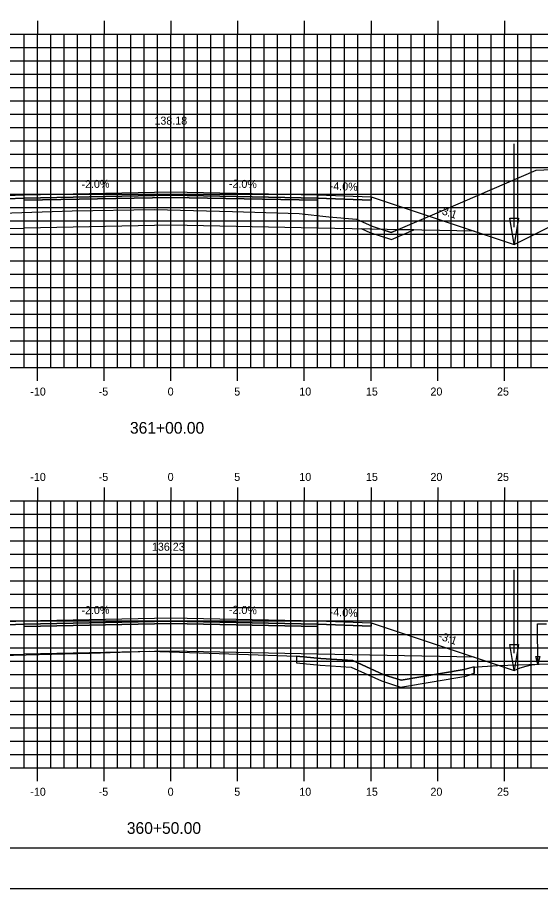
# Model space of a CAD drawing. Extents: x 1146525 to 1146695, y 608981 to 609091.
# Drawn here: x 1146596.2 to 1146635.4, y 608981.3 to 609046.6 of the extents above; entities that cross this region are included whole.
import ezdxf

# ---------------------------------------------------------------- set-up
doc = ezdxf.new("R2010")
doc.units = 0
for name, color, linetype in [('ANNOTATION', 7, 'Continuous'), ('BORDER', 7, 'Continuous'), ('D_Drainage_Ditch_Line', 7, 'Continuous'), ('D_Roadway_Centerline', 7, 'Continuous'), ('D_Roadway_Centerline_Text', 7, 'Continuous'), ('D_Roadway_Edge_Shoulder', 7, 'Continuous'), ('D_Roadway_Edge_TW', 7, 'Continuous'), ('D_Roadway_Pavement', 7, 'Continuous'), ('D_Roadway_SlopeLines', 7, 'Continuous'), ('D_Roadway_SubGrade', 7, 'Continuous'), ('D_Text_Standard', 7, 'Continuous'), ('H_V ANNOTATION', 7, 'Continuous'), ('MAJOR', 7, 'Continuous'), ('MINOR', 7, 'Continuous'), ('PLOT BOUNDARY', 7, 'Continuous'), ('S_Roadway_Centerline', 7, 'Continuous'), ('SHADING', 7, 'Continuous')]:
    doc.layers.add(name, color=color, linetype=linetype)

msp = doc.modelspace()

# ---------------------------------------------------------------- linework, layer by layer
for points in [[(1146573.905, 609032.428), (1146575.155, 609032.306), (1146576.405, 609032.04), (1146577.655, 609031.631), (1146578.905, 609031.077), (1146581.947, 609029.556), (1146584.947, 609030.556), (1146592.67, 609033.131), (1146592.671, 609033.131), (1146596.671, 609033.291), (1146607.671, 609033.511), (1146618.671, 609033.291), (1146622.671, 609033.131), (1146630.395, 609030.556), (1146633.395, 609029.556), (1146642.977, 609034.348), (1146644.227, 609034.902), (1146645.477, 609035.313), (1146646.727, 609035.583), (1146647.977, 609035.71)], [(1146573.921, 608998.789), (1146575.081, 608998.68), (1146576.241, 608998.437), (1146577.401, 608998.059), (1146578.562, 608997.547), (1146581.562, 608998.547), (1146589.055, 609001.044), (1146589.056, 609001.044), (1146596.671, 609001.349), (1146607.671, 609001.569), (1146618.671, 609001.349), (1146622.671, 609001.189), (1146630.395, 608998.614), (1146633.395, 608997.614), (1146633.841, 608997.812), (1146634.287, 608997.957), (1146634.734, 608998.049), (1146635.18, 608998.09)]]:
    msp.add_lwpolyline(points)
at = {"layer": 'BORDER'}
msp.add_lwpolyline([(1146532.671, 608984.335), (1146692.671, 608984.335), (1146692.671, 609089.335), (1146532.671, 609089.335)], close=True, dxfattribs=at)
at = {"layer": 'D_Drainage_Ditch_Line'}
for p, q in [((1146633.395, 609030.869), (1146633.395, 609037.112)), ((1146633.395, 608998.927), (1146633.395, 609005.17))]:
    msp.add_line(p, q, dxfattribs=at)
for points in [[(1146633.067, 609031.525), (1146633.723, 609031.525), (1146633.395, 609029.556)], [(1146633.067, 608999.583), (1146633.723, 608999.583), (1146633.395, 608997.614)]]:
    msp.add_lwpolyline(points, close=True, dxfattribs=at)
at = {"layer": 'D_Roadway_Edge_Shoulder'}
for points in [[(1146596.671, 609033.291), (1146592.671, 609033.131), (1146592.671, 609032.881), (1146596.671, 609033.041)], [(1146618.671, 609033.291), (1146622.671, 609033.131), (1146622.671, 609032.881), (1146618.671, 609033.041)], [(1146596.671, 609001.349), (1146590.841, 609001.116), (1146590.841, 609000.866), (1146596.671, 609001.099)], [(1146618.671, 609001.349), (1146622.671, 609001.189), (1146622.671, 609000.939), (1146618.671, 609001.099)]]:
    msp.add_lwpolyline(points, close=True, dxfattribs=at)
at = {"layer": 'D_Roadway_Edge_TW'}
for points in [[(1146596.671, 609033.041), (1146596.671, 609033.291), (1146607.671, 609033.511), (1146618.671, 609033.291), (1146618.671, 609033.041), (1146607.671, 609033.261)], [(1146596.671, 609001.099), (1146596.671, 609001.349), (1146607.671, 609001.569), (1146618.671, 609001.349), (1146618.671, 609001.099), (1146607.671, 609001.319)]]:
    msp.add_lwpolyline(points, close=True, dxfattribs=at)
at = {"layer": 'D_Roadway_Pavement'}
for points in [[(1146596.671, 609032.874), (1146596.671, 609033.041), (1146607.671, 609033.261), (1146618.671, 609033.041), (1146618.671, 609032.874), (1146607.671, 609033.094)], [(1146596.671, 609000.932), (1146596.671, 609001.099), (1146607.671, 609001.319), (1146618.671, 609001.099), (1146618.671, 609000.932), (1146607.671, 609001.152)]]:
    msp.add_lwpolyline(points, close=True, dxfattribs=at)
at = {"layer": 'D_Roadway_SlopeLines'}
for points in [[(1146633.395, 609029.556), (1146642.977, 609034.348), (1146644.227, 609034.902), (1146645.477, 609035.313), (1146646.727, 609035.583), (1146647.977, 609035.71)], [(1146630.395, 609030.556), (1146633.395, 609029.556)], [(1146630.395, 608998.614), (1146633.395, 608997.614)], [(1146633.395, 608997.614), (1146633.841, 608997.812), (1146634.287, 608997.957), (1146634.734, 608998.049), (1146635.18, 608998.09)]]:
    msp.add_lwpolyline(points, dxfattribs=at)
at = {"layer": 'D_Roadway_SubGrade'}
for p, q in [((1146617.098, 608998.7), (1146617.098, 608998.2)), ((1146630.395, 608997.893), (1146630.395, 608997.393))]:
    msp.add_line(p, q, dxfattribs=at)
for points in [[(1146596.671, 609032.874), (1146596.671, 609033.041), (1146592.671, 609032.881), (1146592.671, 609033.131), (1146592.67, 609033.131), (1146584.947, 609030.556), (1146596.671, 609030.791)], [(1146596.671, 609030.791), (1146596.671, 609032.874), (1146607.671, 609033.094), (1146618.671, 609032.874), (1146618.671, 609030.791), (1146607.671, 609031.011)], [(1146618.671, 609032.874), (1146618.671, 609033.041), (1146622.671, 609032.881), (1146622.671, 609033.131), (1146622.671, 609033.131), (1146630.395, 609030.556), (1146618.671, 609030.791)], [(1146596.671, 609000.932), (1146596.671, 609001.099), (1146590.841, 609000.866), (1146590.841, 609001.116), (1146590.84, 609001.116), (1146583.233, 608998.58), (1146596.671, 608998.849)], [(1146596.671, 608998.849), (1146596.671, 609000.932), (1146607.671, 609001.152), (1146618.671, 609000.932), (1146618.671, 608998.849), (1146607.671, 608999.069)], [(1146618.671, 609000.932), (1146618.671, 609001.099), (1146622.671, 609000.939), (1146622.671, 609001.189), (1146622.671, 609001.189), (1146630.395, 608998.614), (1146618.671, 608998.849)]]:
    msp.add_lwpolyline(points, close=True, dxfattribs=at)
for points in [[(1146621.982, 609030.725), (1146622.578, 609030.463), (1146624.206, 609029.935), (1146625.88, 609030.647)], [(1146621.982, 609030.725), (1146622.578, 609030.463), (1146624.206, 609029.935), (1146625.88, 609030.647)], [(1146617.098, 608998.199), (1146618.862, 608998.035), (1146621.178, 608997.872), (1146623.445, 608996.845), (1146624.881, 608996.377), (1146629.778, 608997.211), (1146630.334, 608997.39), (1146630.395, 608997.393)]]:
    msp.add_lwpolyline(points, dxfattribs=at)
at = {"layer": 'D_Text_Standard'}
msp.add_lwpolyline([(1146635.18, 608998.09), (1146635.15, 609001.127), (1146635.83, 609001.127)], dxfattribs=at)
msp.add_lwpolyline([(1146635.18, 608998.09), (1146635.029, 608998.671), (1146635.32, 608998.674)], close=True, dxfattribs=at)
at = {"layer": 'MAJOR'}
for p, q in [((1146597.671, 609046.337), (1146597.671, 609045.335)), ((1146602.671, 609046.337), (1146602.671, 609045.335)), ((1146607.671, 609046.337), (1146607.671, 609045.335)), ((1146612.671, 609046.337), (1146612.671, 609045.335)), ((1146617.671, 609046.337), (1146617.671, 609045.335)), ((1146622.671, 609046.337), (1146622.671, 609045.335)), ((1146627.671, 609046.337), (1146627.671, 609045.335)), ((1146632.671, 609046.337), (1146632.671, 609045.335)), ((1146537.671, 609045.335), (1146677.671, 609045.335)), ((1146537.671, 609045.335), (1146677.671, 609045.335)), ((1146597.671, 609020.335), (1146597.671, 609045.335)), ((1146602.671, 609020.335), (1146602.671, 609045.335)), ((1146607.671, 609020.335), (1146607.671, 609045.335)), ((1146612.671, 609020.335), (1146612.671, 609045.335)), ((1146617.671, 609020.335), (1146617.671, 609045.335)), ((1146622.671, 609020.335), (1146622.671, 609045.335)), ((1146627.671, 609020.335), (1146627.671, 609045.335)), ((1146632.671, 609020.335), (1146632.671, 609045.335)), ((1146537.671, 609040.335), (1146677.671, 609040.335)), ((1146537.671, 609035.335), (1146677.671, 609035.335)), ((1146537.671, 609030.335), (1146677.671, 609030.335)), ((1146537.671, 609025.335), (1146677.671, 609025.335)), ((1146537.671, 609020.335), (1146677.671, 609020.335)), ((1146537.671, 609020.335), (1146677.671, 609020.335)), ((1146597.671, 609019.333), (1146597.671, 609020.335)), ((1146602.671, 609019.333), (1146602.671, 609020.335)), ((1146607.671, 609019.333), (1146607.671, 609020.335)), ((1146612.671, 609019.333), (1146612.671, 609020.335)), ((1146617.671, 609019.333), (1146617.671, 609020.335)), ((1146622.671, 609019.333), (1146622.671, 609020.335)), ((1146627.671, 609019.333), (1146627.671, 609020.335)), ((1146632.671, 609019.333), (1146632.671, 609020.335)), ((1146597.671, 609011.337), (1146597.671, 609010.335)), ((1146602.671, 609011.337), (1146602.671, 609010.335)), ((1146607.671, 609011.337), (1146607.671, 609010.335)), ((1146612.671, 609011.337), (1146612.671, 609010.335)), ((1146617.671, 609011.337), (1146617.671, 609010.335)), ((1146622.671, 609011.337), (1146622.671, 609010.335)), ((1146627.671, 609011.337), (1146627.671, 609010.335)), ((1146632.671, 609011.337), (1146632.671, 609010.335)), ((1146537.671, 609010.335), (1146677.671, 609010.335)), ((1146537.671, 609010.335), (1146677.671, 609010.335)), ((1146597.671, 608990.335), (1146597.671, 609010.335)), ((1146602.671, 608990.335), (1146602.671, 609010.335)), ((1146607.671, 608990.335), (1146607.671, 609010.335)), ((1146612.671, 608990.335), (1146612.671, 609010.335)), ((1146617.671, 608990.335), (1146617.671, 609010.335)), ((1146622.671, 608990.335), (1146622.671, 609010.335)), ((1146627.671, 608990.335), (1146627.671, 609010.335)), ((1146632.671, 608990.335), (1146632.671, 609010.335)), ((1146537.671, 609005.335), (1146677.671, 609005.335)), ((1146537.671, 609000.335), (1146677.671, 609000.335)), ((1146537.671, 608995.335), (1146677.671, 608995.335)), ((1146537.671, 608990.335), (1146677.671, 608990.335)), ((1146537.671, 608990.335), (1146677.671, 608990.335)), ((1146597.671, 608989.333), (1146597.671, 608990.335)), ((1146602.671, 608989.333), (1146602.671, 608990.335)), ((1146607.671, 608989.333), (1146607.671, 608990.335)), ((1146612.671, 608989.333), (1146612.671, 608990.335)), ((1146617.671, 608989.333), (1146617.671, 608990.335)), ((1146622.671, 608989.333), (1146622.671, 608990.335)), ((1146627.671, 608989.333), (1146627.671, 608990.335)), ((1146632.671, 608989.333), (1146632.671, 608990.335))]:
    msp.add_line(p, q, dxfattribs=at)
at = {"layer": 'MINOR'}
for p, q in [((1146596.671, 609020.335), (1146596.671, 609045.335)), ((1146598.671, 609020.335), (1146598.671, 609045.335)), ((1146599.671, 609020.335), (1146599.671, 609045.335)), ((1146600.671, 609020.335), (1146600.671, 609045.335)), ((1146601.671, 609020.335), (1146601.671, 609045.335)), ((1146603.671, 609020.335), (1146603.671, 609045.335)), ((1146604.671, 609020.335), (1146604.671, 609045.335)), ((1146605.671, 609020.335), (1146605.671, 609045.335)), ((1146606.671, 609020.335), (1146606.671, 609045.335)), ((1146608.671, 609020.335), (1146608.671, 609045.335)), ((1146609.671, 609020.335), (1146609.671, 609045.335)), ((1146610.671, 609020.335), (1146610.671, 609045.335)), ((1146611.671, 609020.335), (1146611.671, 609045.335)), ((1146613.671, 609020.335), (1146613.671, 609045.335)), ((1146614.671, 609020.335), (1146614.671, 609045.335)), ((1146615.671, 609020.335), (1146615.671, 609045.335)), ((1146616.671, 609020.335), (1146616.671, 609045.335)), ((1146618.671, 609020.335), (1146618.671, 609045.335)), ((1146619.671, 609020.335), (1146619.671, 609045.335)), ((1146620.671, 609020.335), (1146620.671, 609045.335)), ((1146621.671, 609020.335), (1146621.671, 609045.335)), ((1146623.671, 609020.335), (1146623.671, 609045.335)), ((1146624.671, 609020.335), (1146624.671, 609045.335)), ((1146625.671, 609020.335), (1146625.671, 609045.335)), ((1146626.671, 609020.335), (1146626.671, 609045.335)), ((1146628.671, 609020.335), (1146628.671, 609045.335)), ((1146629.671, 609020.335), (1146629.671, 609045.335)), ((1146630.671, 609020.335), (1146630.671, 609045.335)), ((1146631.671, 609020.335), (1146631.671, 609045.335)), ((1146633.671, 609020.335), (1146633.671, 609045.335)), ((1146634.671, 609020.335), (1146634.671, 609045.335)), ((1146537.671, 609044.335), (1146677.671, 609044.335)), ((1146537.671, 609043.335), (1146677.671, 609043.335)), ((1146537.671, 609042.335), (1146677.671, 609042.335)), ((1146537.671, 609041.335), (1146677.671, 609041.335)), ((1146537.671, 609039.335), (1146677.671, 609039.335)), ((1146537.671, 609038.335), (1146677.671, 609038.335)), ((1146537.671, 609037.335), (1146677.671, 609037.335)), ((1146537.671, 609036.335), (1146677.671, 609036.335)), ((1146537.671, 609034.335), (1146677.671, 609034.335)), ((1146537.671, 609033.335), (1146677.671, 609033.335)), ((1146537.671, 609032.335), (1146677.671, 609032.335)), ((1146537.671, 609031.335), (1146677.671, 609031.335)), ((1146537.671, 609029.335), (1146677.671, 609029.335)), ((1146537.671, 609028.335), (1146677.671, 609028.335)), ((1146537.671, 609027.335), (1146677.671, 609027.335)), ((1146537.671, 609026.335), (1146677.671, 609026.335)), ((1146537.671, 609024.335), (1146677.671, 609024.335)), ((1146537.671, 609023.335), (1146677.671, 609023.335)), ((1146537.671, 609022.335), (1146677.671, 609022.335)), ((1146537.671, 609021.335), (1146677.671, 609021.335)), ((1146596.671, 608990.335), (1146596.671, 609010.335)), ((1146598.671, 608990.335), (1146598.671, 609010.335)), ((1146599.671, 608990.335), (1146599.671, 609010.335)), ((1146600.671, 608990.335), (1146600.671, 609010.335)), ((1146601.671, 608990.335), (1146601.671, 609010.335)), ((1146603.671, 608990.335), (1146603.671, 609010.335)), ((1146604.671, 608990.335), (1146604.671, 609010.335)), ((1146605.671, 608990.335), (1146605.671, 609010.335)), ((1146606.671, 608990.335), (1146606.671, 609010.335)), ((1146608.671, 608990.335), (1146608.671, 609010.335)), ((1146609.671, 608990.335), (1146609.671, 609010.335)), ((1146610.671, 608990.335), (1146610.671, 609010.335)), ((1146611.671, 608990.335), (1146611.671, 609010.335)), ((1146613.671, 608990.335), (1146613.671, 609010.335)), ((1146614.671, 608990.335), (1146614.671, 609010.335)), ((1146615.671, 608990.335), (1146615.671, 609010.335)), ((1146616.671, 608990.335), (1146616.671, 609010.335)), ((1146618.671, 608990.335), (1146618.671, 609010.335)), ((1146619.671, 608990.335), (1146619.671, 609010.335)), ((1146620.671, 608990.335), (1146620.671, 609010.335)), ((1146621.671, 608990.335), (1146621.671, 609010.335)), ((1146623.671, 608990.335), (1146623.671, 609010.335)), ((1146624.671, 608990.335), (1146624.671, 609010.335)), ((1146625.671, 608990.335), (1146625.671, 609010.335)), ((1146626.671, 608990.335), (1146626.671, 609010.335)), ((1146628.671, 608990.335), (1146628.671, 609010.335)), ((1146629.671, 608990.335), (1146629.671, 609010.335)), ((1146630.671, 608990.335), (1146630.671, 609010.335)), ((1146631.671, 608990.335), (1146631.671, 609010.335)), ((1146633.671, 608990.335), (1146633.671, 609010.335)), ((1146634.671, 608990.335), (1146634.671, 609010.335)), ((1146537.671, 609009.335), (1146677.671, 609009.335)), ((1146537.671, 609008.335), (1146677.671, 609008.335)), ((1146537.671, 609007.335), (1146677.671, 609007.335)), ((1146537.671, 609006.335), (1146677.671, 609006.335)), ((1146537.671, 609004.335), (1146677.671, 609004.335)), ((1146537.671, 609003.335), (1146677.671, 609003.335)), ((1146537.671, 609002.335), (1146677.671, 609002.335)), ((1146537.671, 609001.335), (1146677.671, 609001.335)), ((1146537.671, 608999.335), (1146677.671, 608999.335)), ((1146537.671, 608998.335), (1146677.671, 608998.335)), ((1146537.671, 608997.335), (1146677.671, 608997.335)), ((1146537.671, 608996.335), (1146677.671, 608996.335)), ((1146537.671, 608994.335), (1146677.671, 608994.335)), ((1146537.671, 608993.335), (1146677.671, 608993.335)), ((1146537.671, 608992.335), (1146677.671, 608992.335)), ((1146537.671, 608991.335), (1146677.671, 608991.335))]:
    msp.add_line(p, q, dxfattribs=at)
at = {"layer": 'PLOT BOUNDARY'}
msp.add_lwpolyline([(1146524.578, 608981.276), (1146694.578, 608981.276), (1146694.578, 609091.276), (1146524.578, 609091.276)], close=True, dxfattribs=at)
at = {"layer": 'S_Roadway_Centerline'}
for points in [[(1146557.189, 609033.149), (1146565.05, 609032.785), (1146581.825, 609032.109), (1146584.311, 609031.657), (1146589.374, 609030.827), (1146592.033, 609031.484), (1146593.468, 609031.837), (1146594.03, 609031.88), (1146595.014, 609031.905), (1146600.278, 609032.092), (1146606.448, 609032.182), (1146612.282, 609032.042), (1146617.286, 609031.872), (1146619.517, 609031.64), (1146621.574, 609031.449), (1146622.756, 609030.931), (1146624.182, 609030.468), (1146629.549, 609032.75), (1146635.043, 609035.129), (1146648.103, 609035.716), (1146654.911, 609035.417)], [(1146558.972, 608999.325), (1146561.084, 608999.24), (1146581.4, 608998.525), (1146588.809, 608997.707), (1146588.862, 608997.698), (1146592.979, 608998.756), (1146592.988, 608998.759), (1146592.993, 608998.758), (1146594.907, 608998.757), (1146601.66, 608998.911), (1146606.094, 608999.07), (1146612.762, 608998.848), (1146617.098, 608998.7), (1146618.903, 608998.533), (1146621.302, 608998.363), (1146623.626, 608997.311), (1146624.919, 608996.889), (1146629.659, 608997.697), (1146630.243, 608997.884), (1146632.151, 608997.991), (1146654.81, 608998.736), (1146655.932, 608998.78), (1146656.093, 608998.782)]]:
    msp.add_lwpolyline(points, dxfattribs=at)
at = {"layer": 'SHADING'}
for p, q in [((1146621.982, 609030.725), (1146622.578, 609030.463)), ((1146623.483, 609030.695), (1146621.982, 609030.725)), ((1146625.88, 609030.647), (1146624.661, 609030.671)), ((1146617.098, 608998.7), (1146617.098, 608998.2)), ((1146630.395, 608997.393), (1146630.395, 608997.893))]:
    msp.add_line(p, q, dxfattribs=at)
for points in [[(1146622.578, 609030.463), (1146624.206, 609029.935), (1146625.88, 609030.647)], [(1146624.661, 609030.671), (1146624.182, 609030.468), (1146623.483, 609030.695)], [(1146630.395, 608997.893), (1146629.659, 608997.697), (1146624.919, 608996.889), (1146623.626, 608997.311), (1146621.302, 608998.363), (1146618.903, 608998.533), (1146617.098, 608998.7)], [(1146617.098, 608998.2), (1146618.862, 608998.035), (1146621.178, 608997.872), (1146623.445, 608996.845), (1146624.881, 608996.377), (1146629.778, 608997.211), (1146630.395, 608997.393)]]:
    msp.add_lwpolyline(points, dxfattribs=at)

# ---------------------------------------------------------------- texts
at = {"layer": 'ANNOTATION'}
for s, rotation, p in [('-2.0%', 1.14576, (1146600.974, 609033.777)), ('-2.0%', 358.85424, (1146612.014, 609033.824)), ('-4.0%', 357.70939, (1146619.567, 609033.656)), ('-3:1', 341.56521, (1146627.683, 609031.915)), ('-2.0%', 1.14576, (1146600.974, 609001.835)), ('-2.0%', 358.85424, (1146612.014, 609001.882)), ('-4.0%', 357.70939, (1146619.567, 609001.714)), ('-3:1', 341.56521, (1146627.683, 608999.973))]:
    msp.add_text(s, height=0.6, rotation=rotation, dxfattribs=at).set_placement(p)
at = {"layer": 'D_Roadway_Centerline'}
for s, p in [('C', (1146607.666, 609033.511)), ('L', (1146607.671, 609033.504)), ('C', (1146607.666, 609001.569)), ('L', (1146607.671, 609001.562))]:
    msp.add_text(s, height=0.0146, dxfattribs=at).set_placement(p)
at = {"layer": 'D_Roadway_Centerline_Text'}
for s, p in [('138.18', (1146606.438, 609038.543)), ('136.23', (1146606.251, 609006.601))]:
    msp.add_text(s, height=0.6, dxfattribs=at).set_placement(p)
at = {"layer": 'H_V ANNOTATION'}
for s, height, p in [('-10', 0.6, (1146597.136, 609018.235)), ('-5', 0.6, (1146602.262, 609018.235)), ('0', 0.6, (1146607.43, 609018.235)), ('5', 0.6, (1146612.422, 609018.235)), ('10', 0.6, (1146617.297, 609018.235)), ('15', 0.6, (1146622.289, 609018.235)), ('20', 0.6, (1146627.125, 609018.235)), ('25', 0.6, (1146632.117, 609018.235)), ('361+00.00', 0.875, (1146604.605, 609015.378)), ('-10', 0.6, (1146597.136, 609011.835)), ('-5', 0.6, (1146602.262, 609011.835)), ('0', 0.6, (1146607.43, 609011.835)), ('5', 0.6, (1146612.422, 609011.835)), ('10', 0.6, (1146617.297, 609011.835)), ('15', 0.6, (1146622.289, 609011.835)), ('20', 0.6, (1146627.125, 609011.835)), ('25', 0.6, (1146632.117, 609011.835)), ('-10', 0.6, (1146597.136, 608988.235)), ('-5', 0.6, (1146602.262, 608988.235)), ('0', 0.6, (1146607.43, 608988.235)), ('5', 0.6, (1146612.422, 608988.235)), ('10', 0.6, (1146617.297, 608988.235)), ('15', 0.6, (1146622.289, 608988.235)), ('20', 0.6, (1146627.125, 608988.235)), ('25', 0.6, (1146632.117, 608988.235)), ('360+50.00', 0.875, (1146604.371, 608985.378))]:
    msp.add_text(s, height=height, dxfattribs=at).set_placement(p)
at = {"layer": 'S_Roadway_Centerline'}
for s, p in [('L', (1146606.44, 609032.175)), ('C', (1146606.443, 609032.182)), ('L', (1146606.086, 608999.062)), ('C', (1146606.089, 608999.07))]:
    msp.add_text(s, height=0.0146, dxfattribs=at).set_placement(p)

doc.saveas('drawing.dxf')
